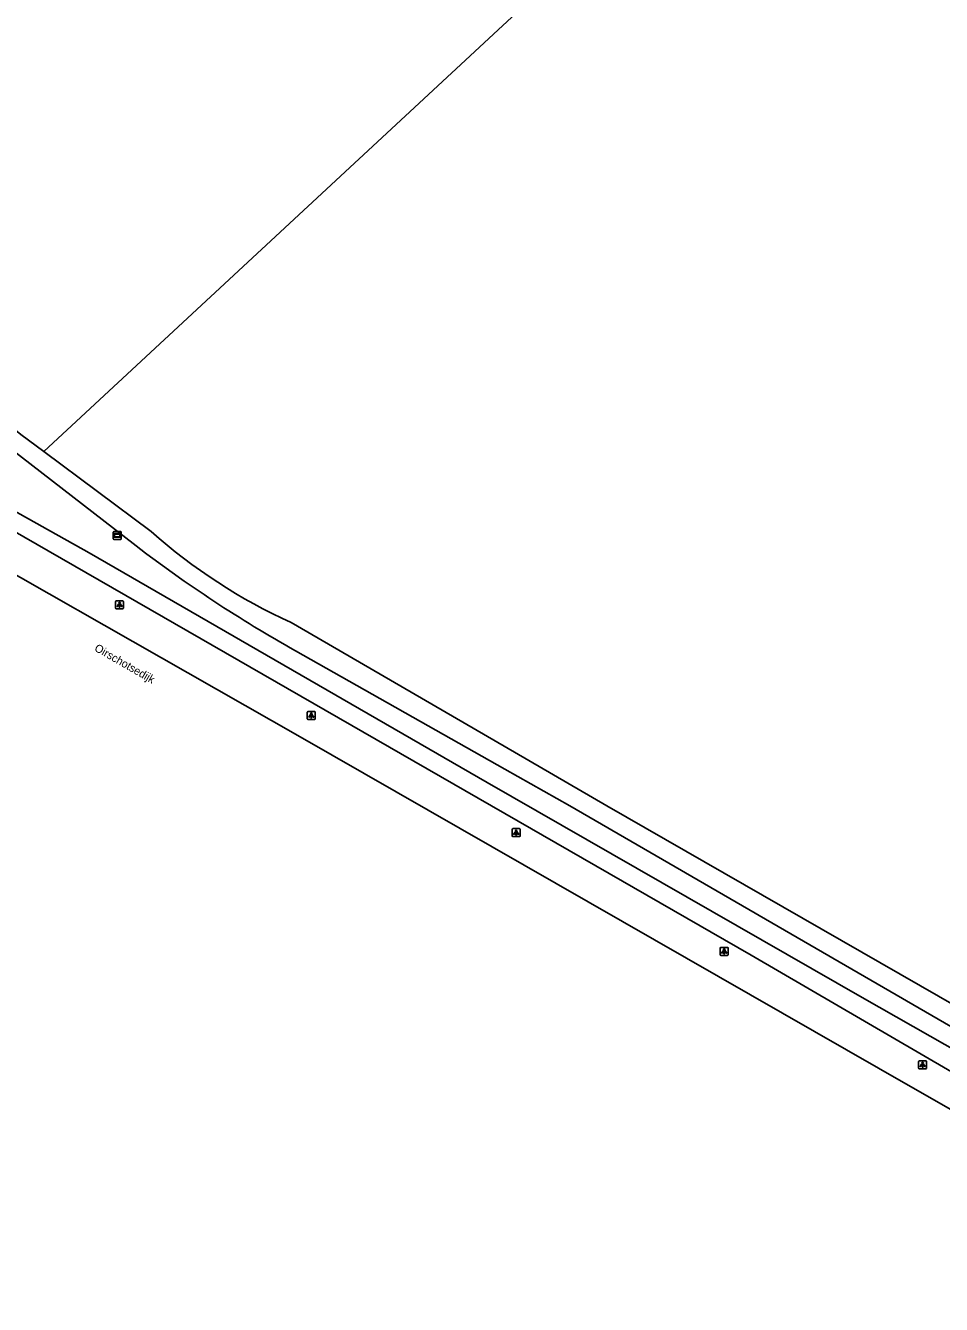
# Model space of a CAD drawing. Extents: x 157154 to 159278, y 385000 to 386650.
# Drawn here: x 157267.4 to 157381.9, y 385937.7 to 386097.5 of the extents above; entities that cross this region are included whole.
import ezdxf

# ---------------------------------------------------------------- set-up
doc = ezdxf.new("R2010")
doc.units = 0
for name, color, linetype in [('IMGEO_Lichtpunt', 7, 'Continuous'), ('IMGEO_Loofbos', 7, 'Continuous'), ('IMGEO_Openbare_ruimte_label', 7, 'Continuous'), ('IMGEO_Rijbaan_lokaal_gesloten', 7, 'Continuous'), ('IMGEO_Verklikker', 7, 'Continuous'), ('IMGEO_Voetpad_open', 7, 'Continuous'), ('IMGEO_Waterloop', 7, 'Continuous')]:
    doc.layers.add(name, color=color, linetype=linetype)

msp = doc.modelspace()

# ---------------------------------------------------------------- linework, layer by layer
at = {"layer": 'IMGEO_Lichtpunt'}
for p, q in [((157278.68, 386025.54), (157278.68, 386024.73)), ((157278.68, 386025.54), (157278.68, 386024.73)), ((157279.58, 386025.64), (157278.77, 386025.64)), ((157279.58, 386025.64), (157278.77, 386025.64)), ((157278.77, 386024.64), (157279.58, 386024.64)), ((157278.77, 386024.64), (157279.58, 386024.64)), ((157279.68, 386024.73), (157279.68, 386025.54)), ((157279.68, 386024.73), (157279.68, 386025.54)), ((157302.64, 386011.71), (157302.64, 386010.9)), ((157302.64, 386011.71), (157302.64, 386010.9)), ((157303.54, 386011.8), (157302.73, 386011.8)), ((157303.54, 386011.8), (157302.73, 386011.8)), ((157303.64, 386010.9), (157303.64, 386011.71)), ((157303.64, 386010.9), (157303.64, 386011.71)), ((157302.73, 386010.81), (157303.54, 386010.81)), ((157302.73, 386010.81), (157303.54, 386010.81)), ((157328.24, 385997.07), (157328.24, 385996.26)), ((157328.24, 385997.07), (157328.24, 385996.26)), ((157329.14, 385997.16), (157328.33, 385997.16)), ((157329.14, 385997.16), (157328.33, 385997.16)), ((157329.23, 385996.26), (157329.23, 385997.07)), ((157329.23, 385996.26), (157329.23, 385997.07)), ((157328.33, 385996.17), (157329.14, 385996.17)), ((157328.33, 385996.17), (157329.14, 385996.17)), ((157354.23, 385982.22), (157354.23, 385981.41)), ((157354.23, 385982.22), (157354.23, 385981.41)), ((157355.13, 385982.31), (157354.32, 385982.31)), ((157355.13, 385982.31), (157354.32, 385982.31)), ((157354.32, 385981.32), (157355.13, 385981.32)), ((157354.32, 385981.32), (157355.13, 385981.32)), ((157355.22, 385981.41), (157355.22, 385982.22)), ((157355.22, 385981.41), (157355.22, 385982.22)), ((157379.02, 385968.05), (157379.02, 385967.25)), ((157379.02, 385968.05), (157379.02, 385967.25)), ((157379.93, 385968.15), (157379.12, 385968.15)), ((157379.93, 385968.15), (157379.12, 385968.15)), ((157379.12, 385967.15), (157379.93, 385967.15)), ((157379.12, 385967.15), (157379.93, 385967.15)), ((157380.02, 385967.25), (157380.02, 385968.05)), ((157380.02, 385967.25), (157380.02, 385968.05))]:
    msp.add_line(p, q, dxfattribs=at)
for points in [[(157279.05, 386025.2), (157279.09, 386025.18), (157278.9, 386024.91), (157278.87, 386024.94), (157279.05, 386025.2)], [(157279.15, 386025.16), (157279.2, 386025.16), (157279.2, 386024.83), (157279.15, 386024.83), (157279.15, 386025.16)], [(157279.26, 386025.18), (157279.3, 386025.2), (157279.49, 386024.94), (157279.45, 386024.91), (157279.26, 386025.18)], [(157303.01, 386011.37), (157303.05, 386011.34), (157302.86, 386011.08), (157302.83, 386011.11), (157303.01, 386011.37)], [(157303.11, 386011.32), (157303.16, 386011.32), (157303.16, 386011), (157303.11, 386011), (157303.11, 386011.32)], [(157303.22, 386011.34), (157303.26, 386011.37), (157303.45, 386011.11), (157303.41, 386011.08), (157303.22, 386011.34)], [(157328.61, 385996.73), (157328.65, 385996.71), (157328.46, 385996.44), (157328.42, 385996.47), (157328.61, 385996.73)], [(157328.71, 385996.69), (157328.76, 385996.69), (157328.76, 385996.36), (157328.71, 385996.36), (157328.71, 385996.69)], [(157328.82, 385996.71), (157328.86, 385996.73), (157329.05, 385996.47), (157329.01, 385996.44), (157328.82, 385996.71)], [(157354.6, 385981.88), (157354.64, 385981.86), (157354.45, 385981.59), (157354.41, 385981.62), (157354.6, 385981.88)], [(157354.7, 385981.84), (157354.75, 385981.84), (157354.75, 385981.51), (157354.7, 385981.51), (157354.7, 385981.84)], [(157354.81, 385981.86), (157354.85, 385981.88), (157355.04, 385981.62), (157355, 385981.59), (157354.81, 385981.86)], [(157379.4, 385967.72), (157379.44, 385967.69), (157379.25, 385967.43), (157379.21, 385967.45), (157379.4, 385967.72)], [(157379.5, 385967.67), (157379.55, 385967.67), (157379.55, 385967.35), (157379.5, 385967.35), (157379.5, 385967.67)], [(157379.61, 385967.69), (157379.65, 385967.72), (157379.83, 385967.45), (157379.8, 385967.43), (157379.61, 385967.69)]]:
    msp.add_lwpolyline(points, dxfattribs=at)
for centre in [(157279.18, 386025.34), (157303.14, 386011.51), (157328.74, 385996.87), (157354.73, 385982.02), (157379.52, 385967.85)]:
    msp.add_circle(centre, 0.0994, dxfattribs=at)
for centre, start, end in [((157278.77, 386025.54), 90, 180), ((157278.77, 386025.54), 90, 180), ((157278.77, 386024.73), 180, 270), ((157278.77, 386024.73), 180, 270), ((157279.58, 386025.54), 0, 90), ((157279.58, 386025.54), 0, 90), ((157279.58, 386024.73), 270, 0), ((157279.58, 386024.73), 270, 360), ((157302.73, 386011.71), 90, 180), ((157302.73, 386011.71), 90, 180), ((157303.54, 386011.71), 0, 90), ((157303.54, 386011.71), 0, 90), ((157302.73, 386010.9), 180, 270), ((157302.73, 386010.9), 180, 270), ((157303.54, 386010.9), 270, 0), ((157303.54, 386010.9), 270, 360), ((157328.33, 385997.07), 90, 180), ((157328.33, 385997.07), 90, 180), ((157329.14, 385997.07), 0, 90), ((157329.14, 385997.07), 0, 90), ((157328.33, 385996.26), 180, 270), ((157328.33, 385996.26), 180, 270), ((157329.14, 385996.26), 270, 0), ((157329.14, 385996.26), 270, 360), ((157354.32, 385982.22), 90, 180), ((157354.32, 385982.22), 90, 180), ((157354.32, 385981.41), 180, 270), ((157354.32, 385981.41), 180, 270), ((157355.13, 385982.22), 0, 90), ((157355.13, 385982.22), 0, 90), ((157355.13, 385981.41), 270, 0), ((157355.13, 385981.41), 270, 360), ((157379.12, 385968.05), 90, 180), ((157379.12, 385968.05), 90, 180), ((157379.12, 385967.25), 180, 270), ((157379.12, 385967.25), 180, 270), ((157379.93, 385968.05), 0, 90), ((157379.93, 385968.05), 0, 90), ((157379.93, 385967.25), 270, 0), ((157379.93, 385967.25), 270, 360)]:
    msp.add_arc(centre, 0.0946, start, end, dxfattribs=at)
at = {"layer": 'IMGEO_Loofbos'}
msp.add_lwpolyline([(157269.71, 386044.28), (157329.95, 386100.2), (157465.79, 386228.19)], dxfattribs=at)
at = {"layer": 'IMGEO_Rijbaan_lokaal_gesloten'}
msp.add_lwpolyline([(157425.7, 385937.7), (157378.01, 385964.93), (157301.73, 386008.65), (157245.84, 386040.45)], dxfattribs=at)
at = {"layer": 'IMGEO_Verklikker'}
for p, q in [((157278.4, 386033.4), (157278.4, 386034.2)), ((157278.4, 386034.2), (157278.4, 386033.4)), ((157278.5, 386034.3), (157279.29, 386034.3)), ((157279.29, 386034.3), (157278.5, 386034.3)), ((157279.39, 386034.2), (157279.39, 386033.4)), ((157279.39, 386033.4), (157279.39, 386034.2)), ((157279.29, 386033.3), (157278.5, 386033.3)), ((157278.5, 386033.3), (157279.29, 386033.3))]:
    msp.add_line(p, q, dxfattribs=at)
for points in [[(157278.5, 386034.03), (157279.29, 386034.03), (157279.29, 386033.57), (157278.5, 386033.57), (157278.5, 386034.03)], [(157278.56, 386033.97), (157278.56, 386033.63), (157279.22, 386033.63), (157279.22, 386033.97), (157278.56, 386033.97)]]:
    msp.add_lwpolyline(points, dxfattribs=at)
for centre, start, end in [((157278.5, 386034.2), 90, 180), ((157278.5, 386034.2), 90, 180), ((157279.29, 386034.2), 0, 90), ((157279.29, 386034.2), 360, 90), ((157278.5, 386033.4), 180, 270), ((157278.5, 386033.4), 180, 270), ((157279.29, 386033.4), 270, 0), ((157279.29, 386033.4), 270, 0)]:
    msp.add_arc(centre, 0.1, start, end, dxfattribs=at)
at = {"layer": 'IMGEO_Voetpad_open'}
for points in [[(157211.87, 386068.54), (157226.55, 386059.05), (157238.01, 386052.55), (157275.38, 386031.65), (157325.1, 386002.94), (157371.95, 385976.04), (157409.6, 385954.65), (157433.37, 385941.16)], [(157430.82, 385939.8), (157410.95, 385950.56), (157358.1, 385981.34), (157315.93, 386005.59), (157238.95, 386049.87), (157225.52, 386057.6), (157213.47, 386063.29)]]:
    msp.add_lwpolyline(points, dxfattribs=at)
at = {"layer": 'IMGEO_Waterloop'}
for points in [[(157241.97, 386066.09), (157241.2, 386065.07), (157240.45, 386064.08), (157281.24, 386032.49)], [(157241.97, 386066.09), (157251.75, 386058.64), (157266.83, 386046.41), (157269.71, 386044.28)], [(157269.71, 386044.28), (157283.14, 386034.3)], [(157300.64, 386022.93), (157328.54, 386006.7), (157340.05, 386000), (157430.56, 385948.06)], [(157301.16, 386019.38), (157327.31, 386004.6), (157335.45, 386000), (157382.24, 385972.9), (157430.99, 385945.03)]]:
    msp.add_lwpolyline(points, dxfattribs=at)
for centre, radius, start, end in [((157328.46, 386084.88), 67.91, 228.1345, 245.8077), ((157385.37, 386169), 171.69, 232.6643, 240.6286)]:
    msp.add_arc(centre, radius, start, end, dxfattribs=at)

# ---------------------------------------------------------------- texts
at = {"layer": 'IMGEO_Openbare_ruimte_label'}
msp.add_text('Oirschotsedijk', height=1, rotation=330.0775, dxfattribs=at).set_placement((157275.95, 386019.45))

doc.saveas('drawing.dxf')
